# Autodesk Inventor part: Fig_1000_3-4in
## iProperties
Created: 2010-12
Part Number: Fig_1000_3-4in
Document SubType Name: Modeling
Designer: D Cole
Density: 1 g/cm^3
Author: D Cole
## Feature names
1. Hole1
